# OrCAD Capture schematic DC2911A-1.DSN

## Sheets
1 PAGE1: size B
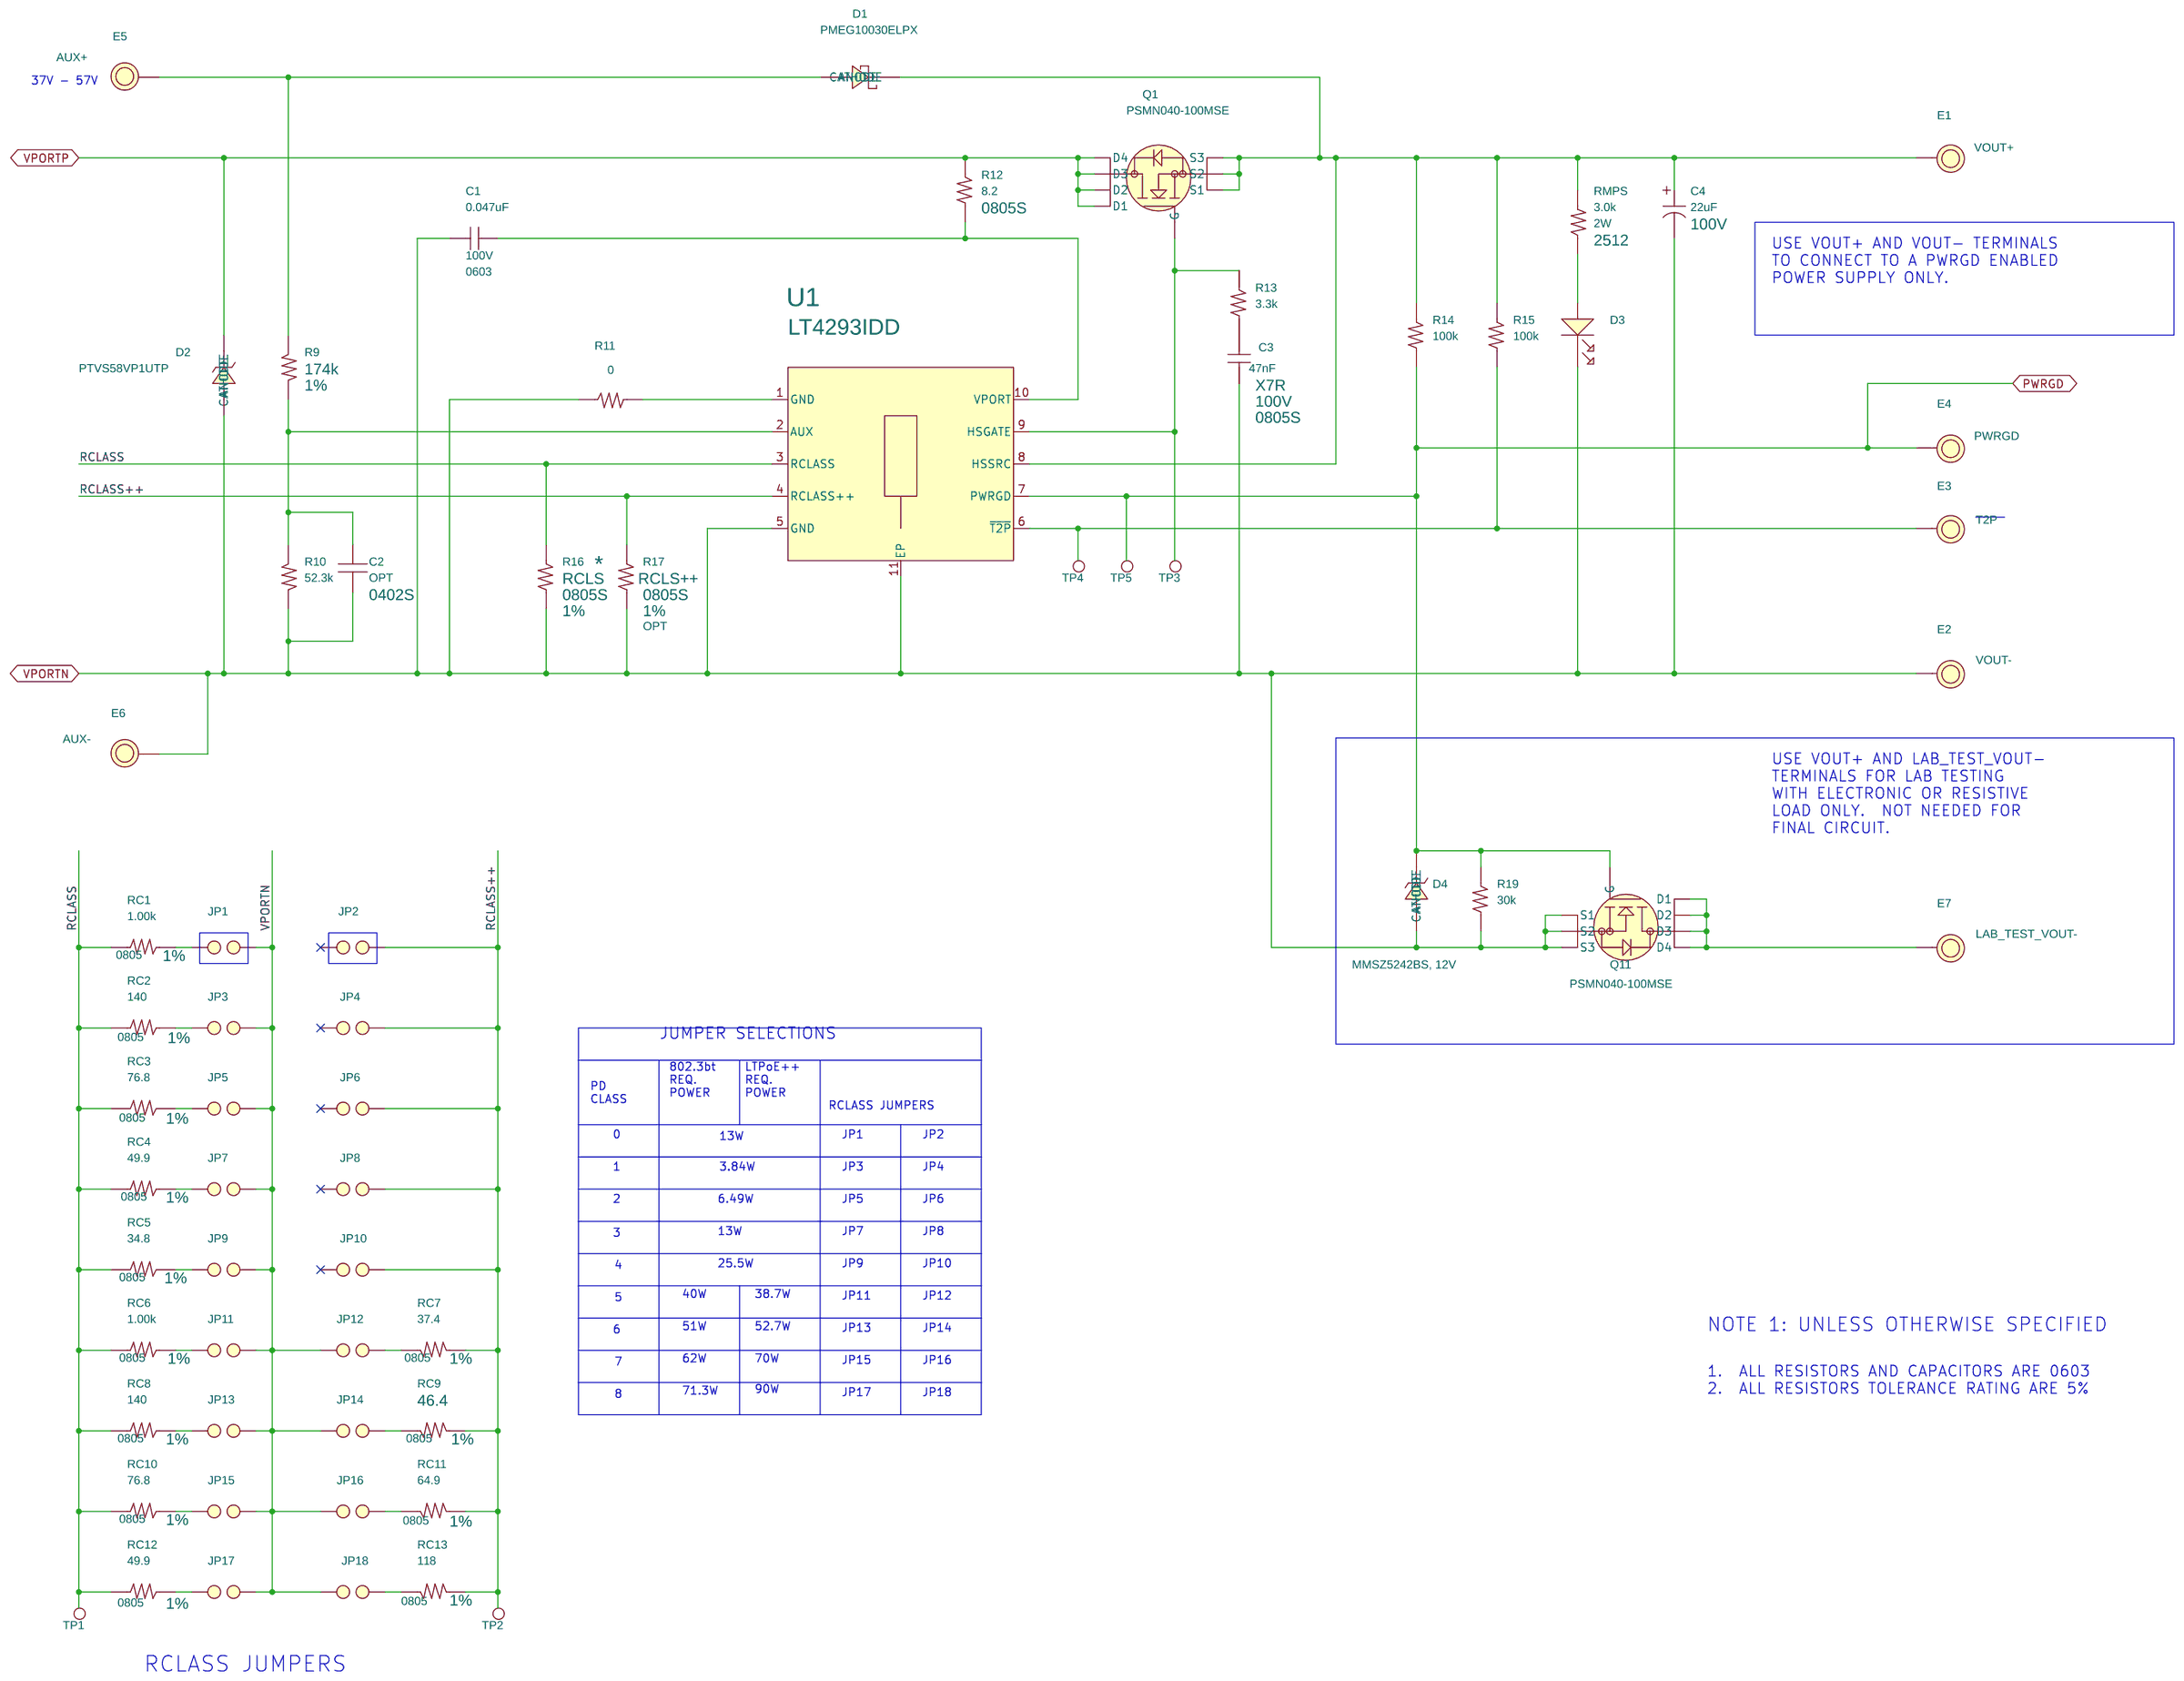
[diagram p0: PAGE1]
2 PAGE2: size B; title: IEEE 802.3bt COMPLIANT, LTPoE++; rev: 1; company: TM; note: DEMO CIRCUIT 2911A; note: KIM T.
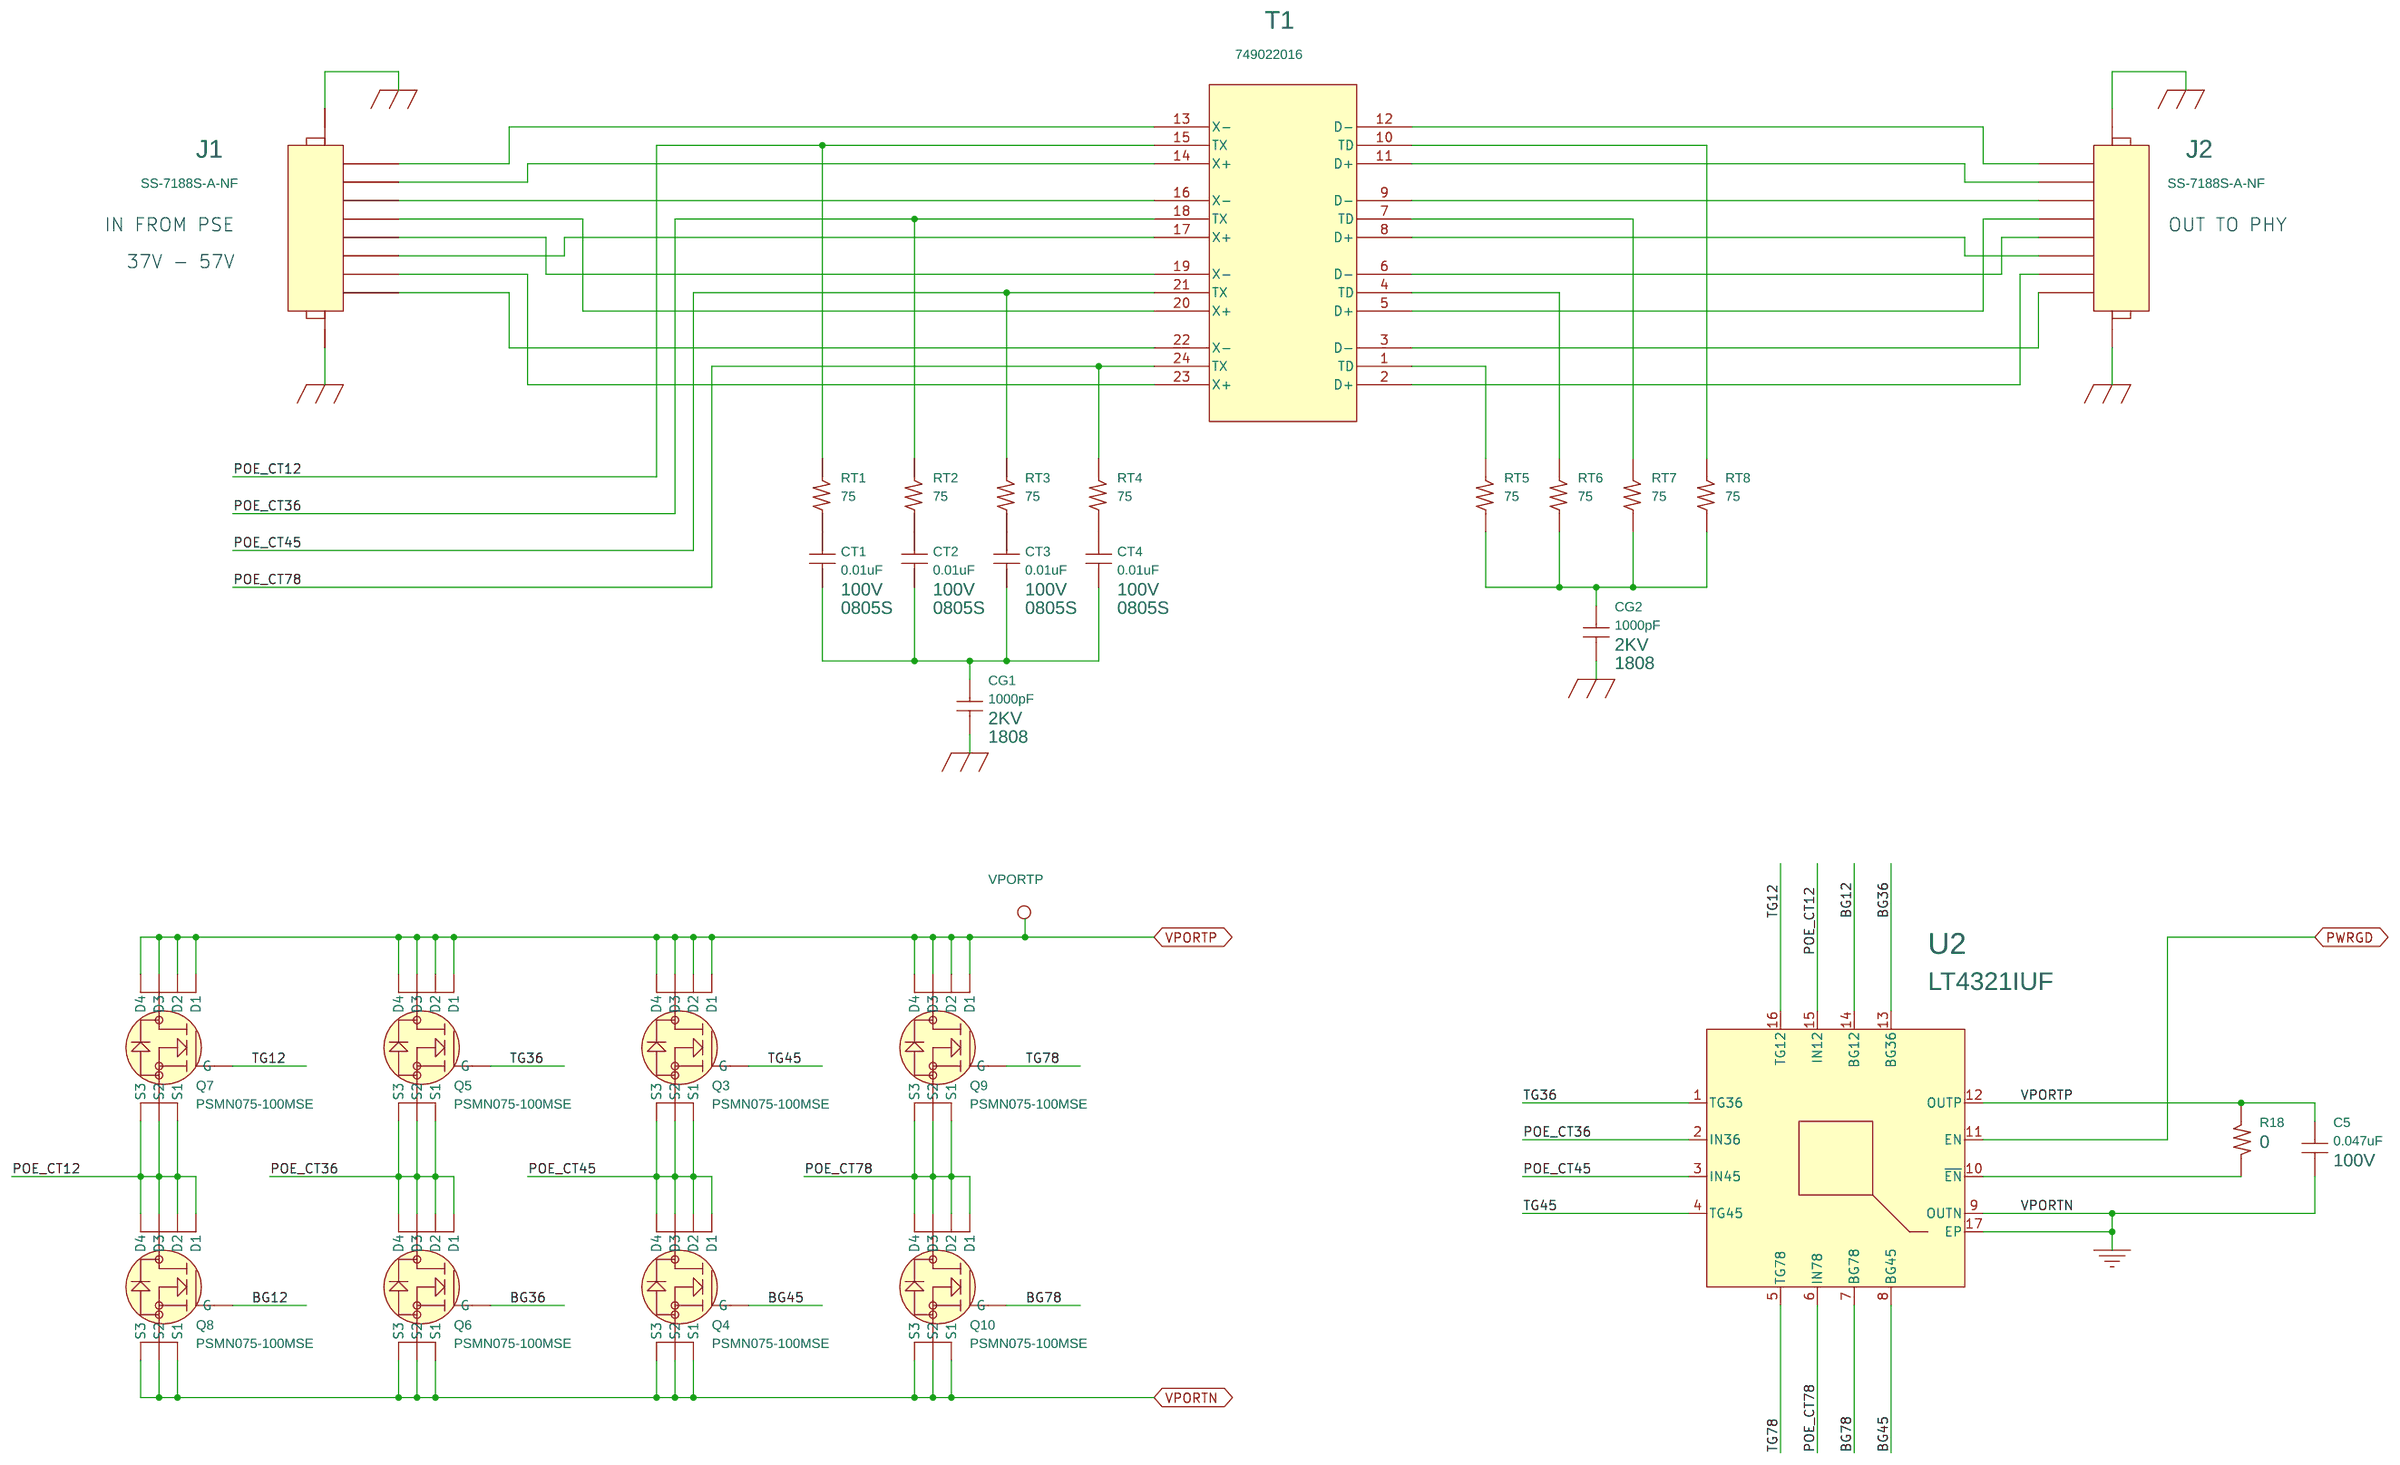
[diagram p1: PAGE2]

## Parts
sheet PAGE1
C1  0.047uF  [0603]
C2  OPT  [0402S]
C3  47nF  [0805S]
C4  22uF  [C-SUNCON-CE-BS-8X10.2]
D1  PMEG10030ELPX  [SOD128]
D2  PTVS58VP1UTP  [SOD128]
D3  WE, 150080GS75000  [LED-WE-GRN-150080GS75000]
D4  MMSZ5242BS, 12V  [SOD323]
E1  PAD150-094  [MILL-MAX-2501-2]
E2  PAD150-094  [MILL-MAX-2501-2]
E3  PAD150-094  [MILL-MAX-2501-2]
E4  PAD150-094  [MILL-MAX-2501-2]
E5  PAD150-094  [MILL-MAX-2501-2]
E6  PAD150-094  [MILL-MAX-2501-2]
E7  PAD150-094  [MILL-MAX-2501-2]
JP1  CommCon-2802s-02g2  [HD1X2-079-REV2]
JP2  CommCon-2802s-02g2  [HD1X2-079-REV2]
JP3  CommCon-2802s-02g2  [HD1X2-079-REV2]
JP4  CommCon-2802s-02g2  [HD1X2-079-REV2]
JP5  CommCon-2802s-02g2  [HD1X2-079-REV2]
JP6  CommCon-2802s-02g2  [HD1X2-079-REV2]
JP7  CommCon-2802s-02g2  [HD1X2-079-REV2]
JP8  CommCon-2802s-02g2  [HD1X2-079-REV2]
JP9  CommCon-2802s-02g2  [HD1X2-079-REV2]
JP10  CommCon-2802s-02g2  [HD1X2-079-REV2]
JP11  CommCon-2802s-02g2  [HD1X2-079-REV2]
JP12  CommCon-2802s-02g2  [HD1X2-079-REV2]
JP13  CommCon-2802s-02g2  [HD1X2-079-REV2]
JP14  CommCon-2802s-02g2  [HD1X2-079-REV2]
JP15  CommCon-2802s-02g2  [HD1X2-079-REV2]
JP16  CommCon-2802s-02g2  [HD1X2-079-REV2]
JP17  CommCon-2802s-02g2  [HD1X2-079-REV2]
JP18  CommCon-2802s-02g2  [HD1X2-079-REV2]
Q1  PSMN040-100MSE  [LFPAK33-8PIN]
Q11  PSMN040-100MSE  [LFPAK33-8PIN]
R9  174k  [0603]
R10  52.3k  [0603]
R11  0  [0603]
R12  8.2  [0805S]
R13  3.3k  [0603]
R14  100k  [0603]
R15  100k  [0603]
R16  *  [0805S]
R17  OPT  [0805S]
R19  30k  [0603]
RC1  1.00k  [0805]
RC2  140  [0805]
RC3  76.8  [0805]
RC4  49.9  [0805]
RC5  34.8  [0805]
RC6  1.00k  [0805]
RC7  37.4  [0805]
RC8  140  [0805]
RC9  46.4  [0805]
RC10  76.8  [0805]
RC11  64.9  [0805]
RC12  49.9  [0805]
RC13  118  [0805]
RMPS  3.0k  [2512]
TP1  E-SMT-060  [SMTP]
TP2  E-SMT-060  [SMTP]
TP3  E-SMT-060  [SMTP]
TP4  E-SMT-060  [SMTP]
TP5  E-SMT-060  [SMTP]
U1  LT4293IDD  [DFN10DD/MSOP10MS]
sheet PAGE2
C5  0.047uF  [0603]
CG1  1000pF  [1808]
CG2  1000pF  [1808]
CT1  0.01uF  [0805S]
CT2  0.01uF  [0805S]
CT3  0.01uF  [0805S]
CT4  0.01uF  [0805S]
J1  SS-7188S-A-NF  [RJ45-STEWART-SS7188S]
J2  SS-7188S-A-NF  [RJ45-STEWART-SS7188S]
Q3  PSMN075-100MSE  [LFPAK33-8PIN]
Q4  PSMN075-100MSE  [LFPAK33-8PIN]
Q5  PSMN075-100MSE  [LFPAK33-8PIN]
Q6  PSMN075-100MSE  [LFPAK33-8PIN]
Q7  PSMN075-100MSE  [LFPAK33-8PIN]
Q8  PSMN075-100MSE  [LFPAK33-8PIN]
Q9  PSMN075-100MSE  [LFPAK33-8PIN]
Q10  PSMN075-100MSE  [LFPAK33-8PIN]
R18  0  [0603]
RT1  75  [0603]
RT2  75  [0603]
RT3  75  [0603]
RT4  75  [0603]
RT5  75  [0603]
RT6  75  [0603]
RT7  75  [0603]
RT8  75  [0603]
T1  749022016  [749022016]
U2  LT4321IUF  [QFN16UF-4X4]
VPORTP  E-SMT-060  [SMTP]

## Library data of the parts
C1 C5 CT1-CT4 = CAP-NP: Voltage Rating: 100V
C2 = CAP_NP
C3 = CAP-NP: Tempco: X7R; Voltage Rating: 100V
C4 = CAP: VOLTAGE: 100V
D1 = DIODE_SCHOTTKY_0: 1st Part: Diode; 2nd Part Type: Schottky; 5th Voltage: 100V; 8th Mfr: NXP
D2 = DIODE_ZENER_0: 1st Part: DIODE; 2nd Part Type: TVS; 5th Voltage: 58; 8th Mfr: NXP
D3 = LED-WE-150080GS75000-GREEN
D4 = DIODE_ZENER_0
E1 = E_1: COMPFIXED: VOUT+; Part #: MILL-MAX 2501-2-00-80-00-00-07-0
E2 = E_1: COMPFIXED: VOUT-; Part #: MILL-MAX 2501-2-00-80-00-00-07-0
E3 = E_1: COMPFIXED: T2P; Part #: MILL-MAX 2501-2-00-80-00-00-07-0
E4 = E_1: COMPFIXED: PWRGD; Part #: MILL-MAX 2501-2-00-80-00-00-07-0
E5 = E_1: COMPFIXED: AUX+; Part #: MILL-MAX 2501-2-00-80-00-00-07-0
E6 = E_1: COMPFIXED: AUX-; Part #: MILL-MAX 2501-2-00-80-00-00-07-0
E7 = E_1: COMPFIXED: LAB_TEST_VOUT-; Part #: MILL-MAX 2501-2-00-80-00-00-07-0
JP1-JP18 = JP1X2-079
Q1 Q3-Q11 = MOSFET_N-DIODE-A-SO8
R9-R11 RC1-RC13 = R: Tolerance: 1%
R12 = R: Size: 0603
R13-R15 R18 R19 RT1-RT8 = R: Tolerance: 5%
R16 = R: Part Reference 2: RCLS; Tolerance: 1%
R17 = R: Part Reference 2: RCLS++; Tolerance: 1%
RMPS = R: POWER: 2W
TP1-TP5 VPORTP = E-SMT-060
U1 = LT4293IDD-DFN10DD-3X3
CG1 CG2 = CAP-NP: Voltage Rating: 2KV
J1 J2 = 8_HEADER_1
T1 = 749022016MOD: Optional: *
U2 = LT4321IUF-QFN16UF-4X4

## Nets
GND_EARTH: CG1.2 CG2.2 J1.9 J1.10 J2.9 J2.10
BG12: Q8.4(G) U2.14(BG12)
BG36: Q6.4(G) U2.13(BG36)
BG45: Q4.4(G) U2.8(BG45)
BG78: Q10.4(G) U2.7(BG78)
POE_CT12: Q7.1(S1) Q7.2(S2) Q7.3(S3) Q8.5(D1) Q8.6(D2) Q8.7(D3) Q8.8(D4) RT1.1 T1.15(TX) U2.15(IN12)
POE_CT36: Q5.1(S1) Q5.2(S2) Q5.3(S3) Q6.5(D1) Q6.6(D2) Q6.7(D3) Q6.8(D4) RT2.1 T1.18(TX) U2.2(IN36)
POE_CT45: Q3.1(S1) Q3.2(S2) Q3.3(S3) Q4.5(D1) Q4.6(D2) Q4.7(D3) Q4.8(D4) RT3.1 T1.21(TX) U2.3(IN45)
POE_CT78: Q9.1(S1) Q9.2(S2) Q9.3(S3) Q10.5(D1) Q10.6(D2) Q10.7(D3) Q10.8(D4) RT4.1 T1.24(TX) U2.6(IN78)
PWRGD: D4.1(CATHODE) E4.1(A) Q11.4(G) R14.2 R19.1 TP5.1 U1.7(PWRGD) U2.11(EN)
RCLASS: R16.1 RC1.2 RC2.2 RC3.2 RC4.2 RC5.2 RC6.2 RC8.2 RC10.2 RC12.2 TP1.1 U1.3(RCLASS)
RCLASS++: JP2.2 JP4.2 JP6.2 JP8.2 JP10.2 R17.1 RC7.2 RC9.2 RC11.2 RC13.2 TP2.1 U1.4(RCLASS++)
TG12: Q7.4(G) U2.16(TG12)
TG36: Q5.4(G) U2.1(TG36)
TG45: Q3.4(G) U2.4(TG45)
TG78: Q9.4(G) U2.5(TG78)
VPORTN: C1.2 C2.2 C3.2 C4.2 C5.2 D2.2(ANODE) D3.1 D4.2(ANODE) E2.1(A) E6.1(A) JP1.1 JP3.1 JP5.1 JP7.1 JP9.1 JP11.1 JP12.1 JP13.1 JP14.1 JP15.1 JP16.1 JP17.1 JP18.1 Q4.1(S1) Q4.2(S2) Q4.3(S3) Q6.1(S1) Q6.2(S2) Q6.3(S3) Q8.1(S1) Q8.2(S2) Q8.3(S3) Q10.1(S1) Q10.2(S2) Q10.3(S3) Q11.1(S1) Q11.2(S2) Q11.3(S3) R10.2 R11.1 R16.2 R17.2 R19.2 U1.5(GND) U1.11(EP) U2.9(OUTN) U2.17(EP)
VPORTP: C5.1 D2.1(CATHODE) Q1.5(D1) Q1.6(D2) Q1.7(D3) Q1.8(D4) Q3.5(D1) Q3.6(D2) Q3.7(D3) Q3.8(D4) Q5.5(D1) Q5.6(D2) Q5.7(D3) Q5.8(D4) Q7.5(D1) Q7.6(D2) Q7.7(D3) Q7.8(D4) Q9.5(D1) Q9.6(D2) Q9.7(D3) Q9.8(D4) R12.1 R18.1 U2.12(OUTP) VPORTP.1
N18356403: C4.1 D1.1(CATHODE) E1.1(A) Q1.1(S1) Q1.2(S2) Q1.3(S3) R14.1 R15.1 RMPS.2 U1.8(HSSRC)
N18381756: C2.1 R9.2 R10.1 U1.2(AUX)
N18399009: E3.1(A) R15.2 TP4.1 U1.6(~{T2P})
N18466967: JP16.2 RC11.1
N18467267: JP14.2 RC9.1
N18469325: JP9.2 RC5.1
N18469327: JP7.2 RC4.1
N18469329: JP5.2 RC3.1
N18469331: JP3.2 RC2.1
N18513312: R11.2 U1.1(GND)
N18720568: Q1.4(G) R13.1 TP3.1 U1.9(HSGATE)
N18885115: D1.2(ANODE) E5.1(A) R9.1
N19880196: C1.1 R12.2 U1.10(VPORT)
N20022949: JP13.2 RC8.1
N20024103: JP15.2 RC10.1
N20036601: JP12.2 RC7.1
N20192650: JP17.2 RC12.1
N20300593: JP18.2 RC13.1
N20454108: E7.1(A) Q11.5(D1) Q11.6(D2) Q11.7(D3) Q11.8(D4)
N20553685: R18.2 U2.10(~{EN})
N20563723: JP1.2 RC1.1
N20563974: JP11.2 RC6.1
N20566005: CG2.1 RT5.2 RT6.2 RT7.2 RT8.2
N20566123: J2.5 T1.6(D-)
N20566125: J2.8 T1.3(D-)
N20566127: J2.4 T1.5(D+)
N20566129: J2.7 T1.2(D+)
N20566144: CG1.1 CT1.2 CT2.2 CT3.2 CT4.2
N20566156: J1.2 T1.14(X+)
N20566160: RT5.1 T1.1(TD)
N20566172: RT6.1 T1.4(TD)
N20566182: RT7.1 T1.7(TD)
N20566186: RT8.1 T1.10(TD)
N20566280: J1.1 T1.13(X-)
N20566282: J1.3 T1.16(X-)
N20566286: J1.6 T1.17(X+)
N20566288: J1.5 T1.19(X-)
N20566290: J1.4 T1.20(X+)
N20566292: J1.8 T1.22(X-)
N20566294: J2.1 T1.12(D-)
N20566298: J1.7 T1.23(X+)
N20566300: J2.6 T1.8(D+)
N20566302: J2.3 T1.9(D-)
N20566304: J2.2 T1.11(D+)
N20594840: D3.2 RMPS.1
N20629290: CT2.1 RT2.2
N20629291: CT4.1 RT4.2
N20629292: CT3.1 RT3.2
N20629293: CT1.1 RT1.2
N20629622: C3.1 R13.2

Not connected (* = marked no-connect by the designer): JP2 1*; JP4 1*; JP6 1*; JP8 1*; JP10 1*

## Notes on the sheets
sheet 1
- 37V - 57V
- USE VOUT+ AND VOUT- TERMINALS
  TO CONNECT TO A PWRGD ENABLED
  POWER SUPPLY ONLY.
- USE VOUT+ AND LAB_TEST_VOUT-
  TERMINALS FOR LAB TESTING
  WITH ELECTRONIC OR RESISTIVE
  LOAD ONLY.  NOT NEEDED FOR
  FINAL CIRCUIT.
- JUMPER SELECTIONS
- 802.3bt
  REQ.
  POWER
- LTPoE++
  REQ.
  POWER
- PD
  CLASS
- RCLASS JUMPERS
- 0
- 13W
- JP1
- JP2
- 1
- 3.84W
- JP3
- JP4
- 2
- 6.49W
- JP5
- JP6
- 3
- 13W
- JP7
- JP8
- 25.5W
- JP9
- JP10
- 4
- 5
- 40W
- 38.7W
- JP11
- JP12
- 6
- 51W
- 52.7W
- JP13
- JP14
- NOTE 1: UNLESS OTHERWISE SPECIFIED
- 62W
- 70W
- 7
- JP15
- JP16
- 1.  ALL RESISTORS AND CAPACITORS ARE 0603
  2.  ALL RESISTORS TOLERANCE RATING ARE 5%
- 8
- 71.3W
- 90W
- JP17
- JP18
- RCLASS JUMPERS
sheet 2
- IN FROM PSE
- OUT TO PHY
- 37V - 57V
